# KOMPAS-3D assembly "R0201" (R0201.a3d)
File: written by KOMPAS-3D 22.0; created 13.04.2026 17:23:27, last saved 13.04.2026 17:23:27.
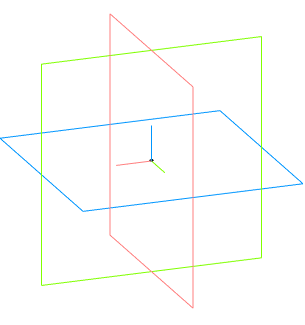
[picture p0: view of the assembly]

Document properties: Автор: Andrey; Полное имя файла: C:\Users\User1\Documents\R0201.a3d

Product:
- Component [detail]: ERA1AEB101C  | qty 1  | source file: ERA1AEB101C.m3d
- Part/product: R0201
    Комментарий: R0201

Referenced files in C:\Users\User1\Documents\: ERA1AEB101C.m3d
